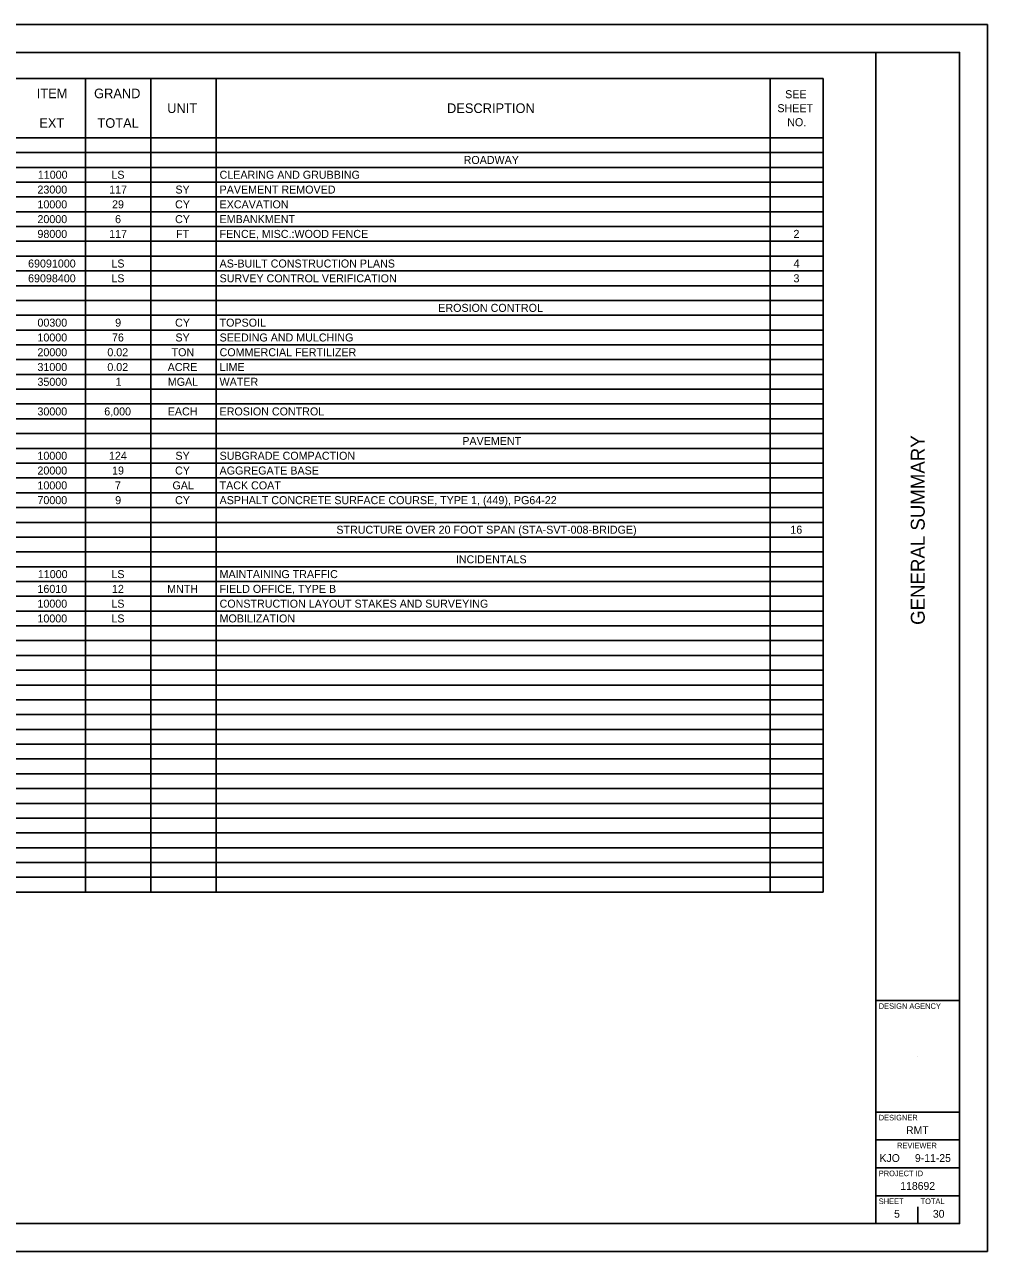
# Model space of a CAD drawing. Extents: x 0 to 34, y 0 to 22.
# Drawn here: x 16.73 to 34, y 0 to 22 of the extents above; entities that cross this region are included whole.
import ezdxf

# ---------------------------------------------------------------- set-up
doc = ezdxf.new("R2010")
doc.units = 0
for name, color, linetype in [('Default', 7, 'Continuous'), ('SH_Border', 7, 'Continuous'), ('SH_Cut_Line', 7, 'Continuous'), ('SH_Data', 7, 'Continuous')]:
    doc.layers.add(name, color=color, linetype=linetype)

msp = doc.modelspace()

# ---------------------------------------------------------------- linework, layer by layer
at = {"layer": 'Default'}
for p, q in [((2.161, 21.03), (31.052, 21.03)), ((17.823, 21.03), (17.823, 6.444)), ((18.993, 21.03), (18.993, 6.444)), ((20.163, 21.03), (20.163, 6.444)), ((30.1, 21.03), (30.1, 6.444)), ((31.052, 21.03), (31.052, 6.444)), ((2.161, 19.969), (31.052, 19.969)), ((2.161, 19.704), (31.052, 19.704)), ((2.161, 19.439), (31.052, 19.439)), ((2.161, 19.174), (31.052, 19.174)), ((2.161, 18.909), (31.052, 18.909)), ((2.161, 18.643), (31.052, 18.643)), ((2.161, 18.378), (31.052, 18.378)), ((2.161, 18.113), (31.052, 18.113)), ((2.161, 17.848), (31.052, 17.848)), ((2.161, 17.583), (31.052, 17.583)), ((2.161, 17.317), (31.052, 17.317)), ((2.161, 17.052), (31.052, 17.052)), ((2.161, 16.787), (31.052, 16.787)), ((2.161, 16.522), (31.052, 16.522)), ((2.161, 16.257), (31.052, 16.257)), ((2.161, 15.991), (31.052, 15.991)), ((2.161, 15.726), (31.052, 15.726)), ((2.161, 15.461), (31.052, 15.461)), ((2.161, 15.196), (31.052, 15.196)), ((2.161, 14.931), (31.052, 14.931)), ((2.161, 14.665), (31.052, 14.665)), ((2.161, 14.4), (31.052, 14.4)), ((2.161, 14.135), (31.052, 14.135)), ((2.161, 13.87), (31.052, 13.87)), ((2.161, 13.605), (31.052, 13.605)), ((2.161, 13.339), (31.052, 13.339)), ((2.161, 13.074), (31.052, 13.074)), ((2.161, 12.809), (31.052, 12.809)), ((2.161, 12.544), (31.052, 12.544)), ((2.161, 12.279), (31.052, 12.279)), ((2.161, 12.013), (31.052, 12.013)), ((2.161, 11.748), (31.052, 11.748)), ((2.161, 11.483), (31.052, 11.483)), ((2.161, 11.218), (31.052, 11.218)), ((2.161, 10.953), (31.052, 10.953)), ((2.161, 10.687), (31.052, 10.687)), ((2.161, 10.422), (31.052, 10.422)), ((2.161, 10.157), (31.052, 10.157)), ((2.161, 9.892), (31.052, 9.892)), ((2.161, 9.627), (31.052, 9.627)), ((2.161, 9.361), (31.052, 9.361)), ((2.161, 9.096), (31.052, 9.096)), ((2.161, 8.831), (31.052, 8.831)), ((2.161, 8.566), (31.052, 8.566)), ((2.161, 8.301), (31.052, 8.301)), ((2.161, 8.035), (31.052, 8.035)), ((2.161, 7.77), (31.052, 7.77)), ((2.161, 7.505), (31.052, 7.505)), ((2.161, 7.24), (31.052, 7.24)), ((2.161, 6.975), (31.052, 6.975)), ((2.161, 6.709), (31.052, 6.709)), ((2.161, 6.444), (31.052, 6.444))]:
    msp.add_line(p, q, dxfattribs=at)
at = {"layer": 'SH_Border'}
for p, q in [((32, 0.5), (32, 21.5)), ((32, 4.5), (33.5, 4.5)), ((32, 2.5), (33.5, 2.5)), ((32, 2), (33.5, 2)), ((32, 1.5), (33.5, 1.5)), ((32, 1), (33.5, 1))]:
    msp.add_line(p, q, dxfattribs=at)
msp.add_lwpolyline([(1.5, 21.5), (33.5, 21.5), (33.5, 0.5), (1.5, 0.5)], close=True, dxfattribs=at)
at = {"layer": 'SH_Cut_Line'}
msp.add_lwpolyline([(0, 0), (34, 0), (34, 22), (0, 22)], close=True, dxfattribs=at)
at = {"layer": 'SH_Data'}
for p, q in [((32.75, 3.5), (32.75, 3.5)), ((32.375, 0.675), (32.375, 0.675)), ((32.75, 0.5), (32.75, 0.8))]:
    msp.add_line(p, q, dxfattribs=at)

# ---------------------------------------------------------------- texts
at = {"layer": 'Default'}
for s, height, p in [('ITEM', 0.1722, (16.946, 20.679)), ('GRAND', 0.1722, (17.975, 20.679)), ('SEE ', 0.1435, (30.371, 20.679)), ('UNIT', 0.1722, (19.286, 20.414)), ('DESCRIPTION', 0.17222, (24.306, 20.414)), ('SHEET ', 0.1435, (30.232, 20.428)), ('EXT', 0.1722, (16.992, 20.148)), ('TOTAL', 0.1722, (18.035, 20.148)), ('NO.', 0.1435, (30.408, 20.177)), ('ROADWAY', 0.1435, (24.604, 19.5)), ('11000', 0.1435, (16.966, 19.235)), ('LS', 0.1435, (18.285, 19.235)), ('CLEARING AND GRUBBING', 0.14352, (20.226, 19.235)), ('23000', 0.1435, (16.959, 18.969)), ('117', 0.1435, (18.245, 18.969)), ('SY', 0.1435, (19.434, 18.969)), ('PAVEMENT REMOVED', 0.14352, (20.226, 18.969)), ('10000', 0.1435, (16.959, 18.704)), ('29', 0.1435, (18.297, 18.704)), ('CY', 0.1435, (19.428, 18.704)), ('EXCAVATION', 0.1435, (20.226, 18.704)), ('20000', 0.1435, (16.959, 18.439)), ('6', 0.144, (18.351, 18.439)), ('CY', 0.1435, (19.428, 18.439)), ('EMBANKMENT', 0.1435, (20.226, 18.439)), ('98000', 0.1435, (16.959, 18.174)), ('117', 0.1435, (18.245, 18.174)), ('FT', 0.1435, (19.446, 18.174)), ('FENCE, MISC.:WOOD FENCE', 0.14352, (20.226, 18.174)), ('2', 0.144, (30.52, 18.174)), ('69091000', 0.1435, (16.791, 17.643)), ('LS', 0.1435, (18.285, 17.643)), ('AS-BUILT CONSTRUCTION PLANS', 0.14352, (20.226, 17.643)), ('4', 0.144, (30.522, 17.643)), ('69098400', 0.1435, (16.791, 17.378)), ('LS', 0.1435, (18.285, 17.378)), ('SURVEY CONTROL VERIFICATION', 0.14352, (20.226, 17.378)), ('3', 0.144, (30.52, 17.378)), ('EROSION CONTROL', 0.14352, (24.149, 16.848)), ('00300', 0.1435, (16.959, 16.583)), ('9', 0.144, (18.353, 16.583)), ('CY', 0.1435, (19.428, 16.583)), ('TOPSOIL', 0.1435, (20.226, 16.583)), ('10000', 0.1435, (16.959, 16.317)), ('76', 0.1435, (18.296, 16.317)), ('SY', 0.1435, (19.434, 16.317)), ('SEEDING AND MULCHING', 0.14352, (20.226, 16.317)), ('20000', 0.1435, (16.959, 16.052)), ('0.02', 0.1435, (18.213, 16.052)), ('TON', 0.1435, (19.365, 16.052)), ('COMMERCIAL FERTILIZER', 0.14352, (20.226, 16.052)), ('31000', 0.1435, (16.959, 15.787)), ('0.02', 0.1435, (18.213, 15.787)), ('ACRE', 0.1435, (19.295, 15.787)), ('LIME', 0.1435, (20.226, 15.787)), ('35000', 0.1435, (16.959, 15.522)), ('1', 0.144, (18.36, 15.522)), ('MGAL', 0.1435, (19.297, 15.522)), ('WATER', 0.1435, (20.226, 15.522)), ('30000', 0.1435, (16.959, 14.991)), ('6,000', 0.1435, (18.157, 14.991)), ('EACH', 0.1435, (19.296, 14.991)), ('EROSION CONTROL', 0.14352, (20.226, 14.991)), ('PAVEMENT', 0.1435, (24.58, 14.461)), ('10000', 0.1435, (16.959, 14.196)), ('124', 0.1435, (18.242, 14.196)), ('SY', 0.1435, (19.434, 14.196)), ('SUBGRADE COMPACTION', 0.14352, (20.226, 14.196)), ('20000', 0.1435, (16.959, 13.931)), ('19', 0.1435, (18.297, 13.931)), ('CY', 0.1435, (19.428, 13.931)), ('AGGREGATE BASE', 0.14352, (20.226, 13.931)), ('10000', 0.1435, (16.959, 13.665)), ('7', 0.144, (18.349, 13.665)), ('GAL', 0.1435, (19.381, 13.665)), ('TACK COAT', 0.1435, (20.226, 13.665)), ('70000', 0.1435, (16.959, 13.4)), ('9', 0.144, (18.353, 13.4)), ('CY', 0.1435, (19.428, 13.4)), ('ASPHALT CONCRETE SURFACE COURSE, TYPE 1, (449), PG64-22', 0.14352, (20.226, 13.4)), ('STRUCTURE OVER 20 FOOT SPAN (STA-SVT-008-BRIDGE)', 0.14352, (22.321, 12.87)), ('16', 0.1435, (30.464, 12.87)), ('INCIDENTALS', 0.14352, (24.464, 12.339)), ('11000', 0.1435, (16.966, 12.074)), ('LS', 0.1435, (18.285, 12.074)), ('MAINTAINING TRAFFIC', 0.14352, (20.226, 12.074)), ('16010', 0.1435, (16.959, 11.809)), ('12', 0.1435, (18.296, 11.809)), ('MNTH', 0.1435, (19.285, 11.809)), ('FIELD OFFICE, TYPE B', 0.14352, (20.226, 11.809)), ('10000', 0.1435, (16.959, 11.544)), ('LS', 0.1435, (18.285, 11.544)), ('CONSTRUCTION LAYOUT STAKES AND SURVEYING', 0.14352, (20.226, 11.544)), ('10000', 0.1435, (16.959, 11.279)), ('LS', 0.1435, (18.285, 11.279)), ('MOBILIZATION', 0.14352, (20.226, 11.279))]:
    msp.add_text(s, height=height, dxfattribs=at).set_placement(p)
at = {"layer": 'SH_Data'}
msp.add_text('GENERAL SUMMARY', height=0.25, rotation=90, dxfattribs=at).set_placement((32.875, 11.235))
for s, height, p in [('DESIGN AGENCY', 0.1, (32.05, 4.35)), ('DESIGNER', 0.1, (32.05, 2.35)), ('RMT', 0.14, (32.54, 2.105)), ('REVIEWER', 0.1, (32.378, 1.85)), ('KJO', 0.14, (32.064, 1.605)), ('9-11-25', 0.14, (32.699, 1.605)), ('PROJECT ID', 0.1, (32.05, 1.35)), ('118692', 0.14, (32.436, 1.105)), ('SHEET', 0.1, (32.05, 0.85)), ('TOTAL', 0.1, (32.8, 0.85)), ('5', 0.14, (32.325, 0.605)), ('30', 0.14, (33.021, 0.605))]:
    msp.add_text(s, height=height, dxfattribs=at).set_placement(p)

doc.saveas('drawing.dxf')
